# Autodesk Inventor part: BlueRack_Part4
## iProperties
Shininess: 64.0
Length Units: 11272
Angle Units: 11279
Time Units: 11290
Mass Units: 11286
Length Display Precision: 3
Angle Display Precision: 2
Compacted: True
Part Number: BlueRack_Part4
Document SubType Name: Modeling
Created: 2004-12
Designer: John Blackburn
Material: Steel, Mild
Manufacturer: Standard
Standards Organization: Custom
Density: 0.0
Volumn: 0.0
Area: 0.0
PropertySet Name: Model Information
Control State: 0
Master: False
Checked Out: False
Author: John Blackburn
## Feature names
1. Extrusion1
2. Extrusion2
3. Hole1
4. Rectangular Pattern1
5. Hole2
6. Rectangular Pattern2
